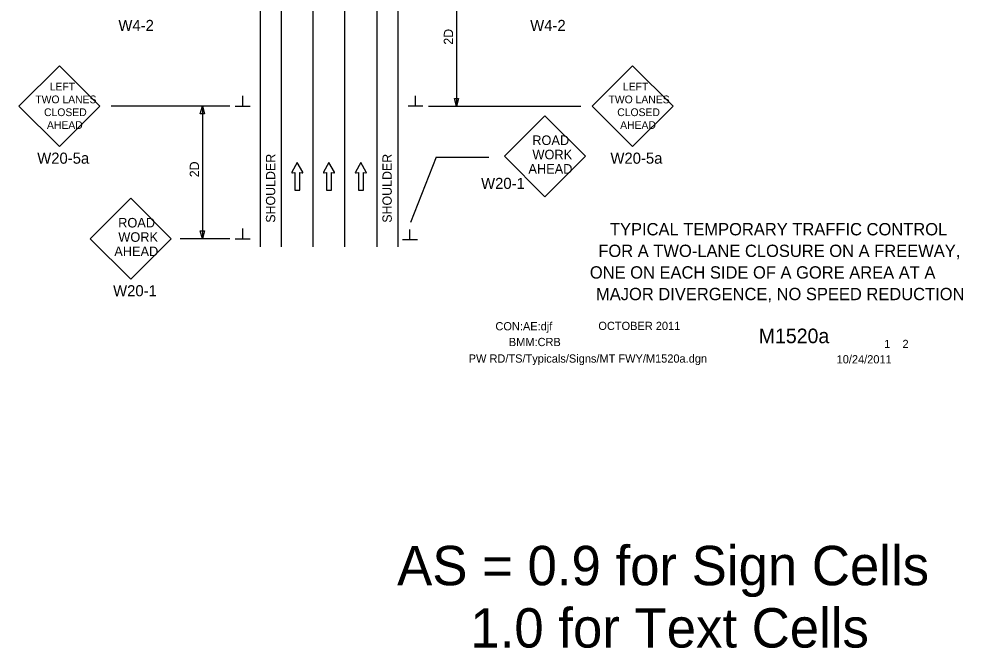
# Model space of a CAD drawing. Extents: x 16731 to 18475, y 7005 to 8303.
# Drawn here: x 16731 to 17443, y 7005 to 7479 of the extents above; entities that cross this region are included whole.
import ezdxf

# ---------------------------------------------------------------- set-up
doc = ezdxf.new("R2010")
doc.units = 0
for name, color, linetype in [('ALI_LEGAL_EX', 7, 'Continuous'), ('BORDER', 7, 'Continuous'), ('BORDER_SIGNAL_WO', 7, 'Continuous'), ('MT_SCRATCH_LEVEL_E', 7, 'Continuous'), ('PAVT_EDGE_EX', 7, 'Continuous'), ('TRAFFIC_SIGNS_PR', 7, 'Continuous'), ('TYPICAL_TEXT_DIMEN_PR', 7, 'Continuous')]:
    doc.layers.add(name, color=color, linetype=linetype)

msp = doc.modelspace()

# ---------------------------------------------------------------- linework, layer by layer
at = {"layer": 'ALI_LEGAL_EX'}
for p, q in [((16953.23, 7307.34), (16953.23, 7890.11)), ((16977.23, 7389.77), (16977.23, 7890.11)), ((16977.23, 7307.34), (16977.23, 7890.11)), ((16977.23, 7307.34), (16977.23, 7890.11))]:
    msp.add_line(p, q, dxfattribs=at)
for points in [[(16953.23, 7379.92), (16953.23, 7404.92)], [(16977.23, 7379.92), (16977.23, 7404.92)]]:
    msp.add_lwpolyline(points, dxfattribs=at)
at = {"layer": 'MT_SCRATCH_LEVEL_E'}
for p, q in [((16941.25, 7370.95), (16937.14, 7363.71)), ((16941.25, 7370.95), (16937.14, 7363.71)), ((16945.4, 7363.71), (16941.25, 7370.95)), ((16945.4, 7363.71), (16941.25, 7370.95)), ((16965.15, 7370.95), (16961.04, 7363.71)), ((16965.15, 7370.95), (16961.04, 7363.71)), ((16969.3, 7363.71), (16965.15, 7370.95)), ((16969.3, 7363.71), (16965.15, 7370.95)), ((16989.21, 7370.95), (16985.1, 7363.71)), ((16989.21, 7370.95), (16985.1, 7363.71)), ((16993.35, 7363.71), (16989.21, 7370.95)), ((16993.35, 7363.71), (16989.21, 7370.95)), ((16937.62, 7363.03), (16939.4, 7363.34)), ((16937.62, 7363.03), (16939.4, 7363.34)), ((16939.4, 7363.34), (16939.4, 7350.08)), ((16939.4, 7363.34), (16939.4, 7350.08)), ((16943.14, 7350.08), (16943.14, 7363.34)), ((16943.14, 7363.34), (16944.92, 7363.03)), ((16943.14, 7350.08), (16943.14, 7363.34)), ((16943.14, 7363.34), (16944.92, 7363.03)), ((16961.53, 7363.03), (16963.3, 7363.34)), ((16961.53, 7363.03), (16963.3, 7363.34)), ((16963.3, 7363.34), (16963.3, 7350.08)), ((16963.3, 7363.34), (16963.3, 7350.08)), ((16967.04, 7350.08), (16967.04, 7363.34)), ((16967.04, 7363.34), (16968.82, 7363.03)), ((16967.04, 7350.08), (16967.04, 7363.34)), ((16967.04, 7363.34), (16968.82, 7363.03)), ((16985.58, 7363.03), (16987.36, 7363.34)), ((16985.58, 7363.03), (16987.36, 7363.34)), ((16987.36, 7363.34), (16987.36, 7350.08)), ((16987.36, 7363.34), (16987.36, 7350.08)), ((16991.1, 7350.08), (16991.1, 7363.34)), ((16991.1, 7363.34), (16992.87, 7363.03)), ((16991.1, 7350.08), (16991.1, 7363.34)), ((16991.1, 7363.34), (16992.87, 7363.03)), ((16939.4, 7350.08), (16943.14, 7350.08)), ((16939.4, 7350.08), (16943.14, 7350.08)), ((16963.3, 7350.08), (16967.04, 7350.08)), ((16963.3, 7350.08), (16967.04, 7350.08)), ((16987.36, 7350.08), (16991.1, 7350.08)), ((16987.36, 7350.08), (16991.1, 7350.08))]:
    msp.add_line(p, q, dxfattribs=at)
for centre, start, end in [((16937.55, 7363.49), 150.42484, 279.96381), ((16937.55, 7363.49), 150.42484, 279.96381), ((16944.99, 7363.49), 260.03619, 29.77312), ((16944.99, 7363.49), 260.03619, 29.77312), ((16961.45, 7363.49), 150.42484, 279.96381), ((16961.45, 7363.49), 150.42484, 279.96381), ((16968.89, 7363.49), 260.03619, 29.77312), ((16968.89, 7363.49), 260.03619, 29.77312), ((16985.5, 7363.49), 150.42484, 279.96381), ((16985.5, 7363.49), 150.42484, 279.96381), ((16992.94, 7363.49), 260.03619, 29.77312), ((16992.94, 7363.49), 260.03619, 29.77312)]:
    msp.add_arc(centre, 0.463, start, end, dxfattribs=at)
at = {"layer": 'PAVT_EDGE_EX'}
for p, q in [((16913.23, 7890.11), (16913.23, 7307.34)), ((16929.23, 7890.11), (16929.23, 7307.34)), ((17001.23, 7890.11), (17001.23, 7307.34)), ((17017.23, 7890.11), (17017.23, 7307.34))]:
    msp.add_line(p, q, dxfattribs=at)
at = {"layer": 'TRAFFIC_SIGNS_PR'}
for p, q in [((16761.96, 7443.98), (16731.42, 7413.44)), ((16792.51, 7413.44), (16761.96, 7443.98)), ((17194.1, 7443.98), (17163.56, 7413.44)), ((17224.65, 7413.44), (17194.1, 7443.98)), ((16731.42, 7413.44), (16761.96, 7382.89)), ((16761.96, 7382.89), (16792.51, 7413.44)), ((17163.56, 7413.44), (17194.1, 7382.89)), ((17194.1, 7382.89), (17224.65, 7413.44)), ((17127.97, 7406.21), (17097.43, 7375.66)), ((17158.52, 7375.66), (17127.97, 7406.21)), ((17097.43, 7375.66), (17127.97, 7345.11)), ((17127.97, 7345.11), (17158.52, 7375.66)), ((16815.76, 7343.98), (16785.22, 7313.44)), ((16846.31, 7313.44), (16815.76, 7343.98)), ((16785.22, 7313.44), (16815.76, 7282.89)), ((16815.76, 7282.89), (16846.31, 7313.44))]:
    msp.add_line(p, q, dxfattribs=at)
at = {"layer": 'TYPICAL_TEXT_DIMEN_PR'}
for p, q in [((17061.33, 7513.44), (17061.33, 7413.44)), ((16900.21, 7413.44), (16900.21, 7421.22)), ((17030.46, 7413.44), (17030.46, 7421.22)), ((17061.33, 7413.44), (17059.76, 7419.3)), ((17059.76, 7419.3), (17061.33, 7419.3)), ((17061.33, 7419.3), (17062.9, 7419.3)), ((17062.9, 7419.3), (17061.33, 7413.44)), ((16890.33, 7413.44), (16800.89, 7413.44)), ((16868.2, 7407.58), (16869.77, 7413.44)), ((16869.77, 7413.44), (16869.77, 7313.44)), ((16869.77, 7413.44), (16871.34, 7407.58)), ((16894.58, 7413.44), (16905.83, 7413.44)), ((17036.08, 7413.44), (17024.83, 7413.44)), ((17040.33, 7413.44), (17155.01, 7413.44)), ((16869.77, 7407.58), (16868.2, 7407.58)), ((16871.34, 7407.58), (16869.77, 7407.58)), ((17046.07, 7375.02), (17026.61, 7325.65)), ((17046.07, 7375.02), (17085.59, 7375.02)), ((16869.77, 7313.44), (16868.2, 7319.3)), ((16868.2, 7319.3), (16869.77, 7319.3)), ((16869.77, 7319.3), (16871.34, 7319.3)), ((16871.34, 7319.3), (16869.77, 7313.44)), ((16900.21, 7313.44), (16900.21, 7321.22)), ((17026.23, 7312.62), (17026.23, 7320.41)), ((16890.33, 7313.44), (16853.05, 7313.44)), ((16894.58, 7313.44), (16905.83, 7313.44)), ((17031.86, 7312.62), (17020.61, 7312.62))]:
    msp.add_line(p, q, dxfattribs=at)

# ---------------------------------------------------------------- texts
at = {"layer": 'BORDER'}
for s, p in [('TYPICAL TEMPORARY TRAFFIC CONTROL', (17177.02, 7315.97)), ('FOR A TWO-LANE CLOSURE ON A FREEWAY,', (17168.26, 7299.66)), ('ONE ON EACH SIDE OF A GORE AREA AT A ', (17161.87, 7283.36)), ('MAJOR DIVERGENCE, NO SPEED REDUCTION', (17166.52, 7267.07))]:
    msp.add_text(s, height=9.3, dxfattribs=at).set_placement(p)
at = {"layer": 'BORDER_SIGNAL_WO'}
for s, height, p in [('CON:AE:djf  ', 6.2, (17090.69, 7244.31)), ('    OCTOBER 2011    ', 6.2, (17159.08, 7244.59)), ('    M1520a   ', 11, (17272.86, 7234.63)), ('BMM:CRB   ', 6.2, (17100.81, 7232.42)), (' 1    2 ', 6.2, (17381.45, 7230.95)), ('PW RD/TS/Typicals/Signs/MT FWY/M1520a.dgn      ', 6.2, (17070.55, 7219.96)), ('10/24/2011    ', 6.2, (17347.93, 7219.38)), ('AS = 0.9 for Sign Cells', 29.7271, (17016.57, 7052)), ('     1.0 for Text Cells', 29.7271, (17016.57, 7004.99))]:
    msp.add_text(s, height=height, dxfattribs=at).set_placement(p)
at = {"layer": 'TRAFFIC_SIGNS_PR'}
for s, height, p in [('W4-2', 8.37, (16806.44, 7470.17)), ('W4-2', 8.37, (17116.9, 7470.17)), ('LEFT', 5.85, (16754.69, 7425.29)), ('LEFT', 5.85, (17186.83, 7425.29)), ('TWO LANES', 5.85, (16743.81, 7415.61)), ('TWO LANES', 5.85, (17175.95, 7415.61)), ('CLOSED', 5.85, (16750.39, 7405.94)), ('CLOSED', 5.85, (17182.53, 7405.94)), ('AHEAD', 5.85, (16752.58, 7396.26)), ('AHEAD', 5.85, (17184.72, 7396.26)), ('ROAD', 7.2, (17118.46, 7384.14)), ('W20-5a', 8.37, (16745.25, 7370.02)), ('WORK', 7.2, (17118.58, 7373.34)), ('W20-5a', 8.37, (17177.39, 7370.02)), ('AHEAD', 7.2, (17115.56, 7362.54)), ('W20-1', 8.37, (17079.87, 7351)), ('ROAD', 7.2, (16806.25, 7321.91)), ('WORK', 7.2, (16806.37, 7311.11)), ('AHEAD', 7.2, (16803.34, 7300.31)), ('W20-1', 8.37, (16802.46, 7270.02))]:
    msp.add_text(s, height=height, dxfattribs=at).set_placement(p)
at = {"layer": 'TYPICAL_TEXT_DIMEN_PR'}
for s, p in [('2D', (17058.77, 7459.8)), ('SHOULDER', (16924.67, 7325.5)), ('SHOULDER', (17012.53, 7325.5)), ('2D', (16867.22, 7359.8))]:
    msp.add_text(s, height=7, rotation=90, dxfattribs=at).set_placement(p)

doc.saveas('drawing.dxf')
